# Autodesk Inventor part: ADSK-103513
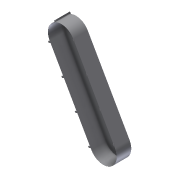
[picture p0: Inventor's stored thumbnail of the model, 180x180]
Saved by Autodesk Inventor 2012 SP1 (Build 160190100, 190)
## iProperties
Shininess: 20.0
Created: 2001-03
Part Number: ADSK-103513
Document SubType Name: Modeling
Designer: Administrator
Stock Number: ADSK-103513
Density: 1 g/cm^3
Material: Default
Density: 0.0
Volumn: 0.0
Area: 0.0
PropertySet Name: Model Information
Control State: 0
Master: False
Checked Out: False
Author: Administrator
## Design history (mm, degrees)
sketch "Sketch1"
  geometry: L1 (158.935, 142.34)-(783.961, -963.211); L2 (-194.841, -57.668)-(430.185, -1163.219); L3 (-17.953, 42.336)-(607.073, -1063.215); A1 r 203.2 centre (-17.953, 42.336) between (158.935, 142.34) and (-194.841, -57.668); A2 r 203.2 centre (607.073, -1063.215) between (430.185, -1163.219) and (783.961, -963.211)
  constraints: 6 end point, 5 point on circle, 4 tangent, 2 centre point
  dimensions: "d11" = 406.4 diameter of A1; "d125" = 1270 distance of L3.end L3.start
extrude "Extrusion1" new body sketch "Sketch1" distance "d5" = 217.17; taper "d6" = 0 deg
shell "Shell1" dims "d7" = 1.5875
sketch "Sketch3"
  geometry: C1 r 50.8 at (17.953, 42.336); A1 r 203.2 centre (17.953, 42.336) between (194.841, -57.668) and (-158.935, 142.34) reference
  constraints: 1 centre point, 1 coincident
  dimensions: "d13" = 101.6 diameter of C1
extrude "Extrusion3" cut sketch "Sketch3" distance "d14" = 25.4; taper "d15" = 0 deg
sketch "Sketch4"
  geometry: L1 (-1.587, 45.689)-(-217.17, 45.689) reference; L2 (-217.17, 45.689)-(-223.52, 45.689); L3 (-223.52, 45.689)-(-198.12, 45.689); L4 (-198.12, 45.689)-(-198.12, 20.289); L5 (-198.12, 20.289)-(-223.52, 20.289); L6 (-223.52, 20.289)-(-223.52, 45.689)
  constraints: 10 end point, 2 parallel, 1 collinear, 1 horizontal, 1 perpendicular
  dimensions: "d18" = 6.35 distance of L1.end L2.end; "d19" = 25.4 distance between parallel lines of L1 L5; "d20" = 25.4 distance between parallel lines of L4 L6
extrude "Extrusion4" join sketch "Sketch4" distance "d21" = 3.175; taper "d22" = 0 deg
sketch "Sketch5"
  geometry: L1 (223.52, 45.689)-(223.52, 20.289) reference; L2 (217.17, 45.689)-(223.52, 45.689) reference; L3 (223.52, 20.289)-(220.345, 20.289); L4 (220.345, 20.289)-(220.345, 45.689); L5 (220.345, 45.689)-(223.52, 45.689); L6 (223.52, 45.689)-(223.52, 20.289)
  constraints: 8 end point, 2 parallel, 1 horizontal, 1 midpoint, 1 perpendicular
  dimensions: "d23" = 3.175 distance between parallel lines of L6 L4 (derived)
extrude "Extrusion5" join sketch "Sketch5" distance "d24" = 22.225; taper "d25" = 0 deg
sketch "Sketch6"
  geometry: L1 (-25.4, 25.4)-(-25.4, 0) reference; L2 (-25.4, 0)-(0, 0) reference; 1 further point
  dimensions: "d26" = 9.525 distance from line of L1 point (-15.875, 12.7); "d27" = 12.7 distance from line of L2 point (-15.875, 12.7)
hole "Hole1" sketch "Sketch6" at (-15.875, 12.7) diameter "d28" = 7.9375; stored, may be unused: countersink angle "d32" = 60 deg, drill point angle "d34" = 118 deg; dims "d29" = 12.7, "d30" = 9.525, "d31" = 6.35, "d33" = 19.05
pattern_linear "Rectangular Pattern1" dims "d37" = 406.4
sketch "Sketch7"
  geometry: L1 (0, 0)-(215.583, 0) reference; L2 (196.533, 0)-(221.933, 0); L3 (221.933, 0)-(221.933, -25.4); L4 (221.933, -25.4)-(196.533, -25.4); L5 (196.533, -25.4)-(196.533, 0); 1 further point; 1 other entity
  constraints: 8 end point, 2 parallel, 1 horizontal, 1 perpendicular, 1 point on line, 1 other
  dimensions: "d38" = 25.4 distance of L2.end L3.end; "d39" = 25.4 distance of L3.end L4.end; "d40" = 6.35 dimension on L3
extrude "Extrusion6" join sketch "Sketch7" distance "d41" = 3.175; taper "d42" = 0 deg
sketch "Sketch8"
  geometry: L1 (-221.933, -25.4)-(-221.933, 0) reference; L2 (-215.583, -25.4)-(-221.933, -25.4) reference; L3 (-221.933, 0)-(-218.758, 0); L4 (-218.758, 0)-(-218.758, -25.4); L5 (-218.758, -25.4)-(-221.933, -25.4); L6 (-221.933, -25.4)-(-221.933, 0)
  constraints: 8 end point, 2 parallel, 1 horizontal, 1 midpoint, 1 perpendicular
extrude "Extrusion7" join sketch "Sketch8" distance "d43" = 22.225; taper "d44" = 0 deg
sketch "Sketch9"
  geometry: L1 (25.4, 0)-(25.4, 25.4) reference; L2 (25.4, 25.4)-(0, 25.4) reference; 1 further point
  dimensions: "d45" = 12.7 distance from line of L2 point (15.875, 12.7); "d46" = 9.525 distance from line of L1 point (15.875, 12.7)
hole "Hole2" sketch "Sketch9" at (15.875, 12.7) diameter "d47" = 7.9375; stored, may be unused: countersink angle "d51" = 60 deg, drill point angle "d53" = 118 deg; dims "d48" = 12.7, "d49" = 9.525, "d50" = 6.35, "d52" = 19.05
pattern_linear "Rectangular Pattern2" dims "d56" = 406.4
sketch "Sketch10"
  geometry: L1 (194.841, -57.668)-(-430.185, -1163.219) reference; L2 (17.953, 42.336)-(-647.399, -1134.544); L3 (17.953, 42.336)-(117.957, 219.224); L4 (-647.399, -1134.544)-(-707.077, -1240.103); L5 (-708.456, -1239.316)-(-648.781, -1133.762); L6 (-648.781, -1133.762)-(16.571, 43.117); L7 (16.571, 43.117)-(116.575, 220.005); L8 (-705.692, -1240.879)-(-646.017, -1135.325); L9 (-646.017, -1135.325)-(19.335, 41.555); L10 (19.335, 41.555)-(119.339, 218.443); L11 (116.575, 220.005)-(119.339, 218.443); L12 (-745.437, -1304.728)-(-743.422, -1307.615); L13 (-708.456, -1239.316)-(-705.692, -1240.879); A1 r 203.2 centre (17.953, 42.336) between (194.841, -57.668) and (-158.935, 142.34) reference; A2 r 203.2 centre (-607.073, -1063.215) between (-783.961, -963.211) and (-430.185, -1163.219) reference
  constraints: 24 end point, 6 collinear, 4 point on circle, 1 parallel, 1 perpendicular, 2 other
  dimensions: "d57" = 1.5875 distance between parallel lines of L2 L6; "d58" = 1.5875 distance between parallel lines of L9 L2
extrude "Extrusion8" join sketch "Sketch10" distance "d59" = 19.05; taper "d60" = 0 deg
sketch "Sketch11"
  geometry: C1 r 50.8 at (5.207, 45.689) reference
extrude "Extrusion9" cut sketch "Sketch11" distance "d61" = 25.4; taper "d62" = 0 deg
sketch "Sketch12"
  geometry: L1 (-27.593, 19.836)-(-124.114, -150.892); L2 (-124.114, -150.892)-(-74.365, -179.018); L3 (-74.365, -179.018)-(22.157, -8.29); A1 r 203.2 centre (17.953, 42.336) between (116.572, 220) and (-158.935, 142.34) reference; A2 r 50.8 centre (17.953, 42.336) between (41.56, 87.318) and (-8.418, -1.083) reference; A3 r 50.8 centre (17.953, 42.336) between (-27.593, 19.836) and (22.157, -8.29)
  constraints: 6 end point, 4 point on circle, 1 centre point, 1 coincident, 1 concentric, 1 parallel, 1 perpendicular
  dimensions: "d65" = 238.125 distance from line of A1.centre L2; "d126" = 57.15 distance between parallel lines of L3 L1; "d127" = 28.575 distance from line of L3 A1.centre (= 0.5 x d126)
extrude "Extrusion10" cut sketch "Sketch12" stored distance "d66" = 50.8; taper "d67" = 0 deg
sketch "Sketch13"
  geometry: L1 (19.05, 0)-(19.05, 152.425) reference; L2 (0, 152.425)-(19.05, 152.425) reference; 2 further points
  dimensions: "d68" = 139.7 distance of point (11.113, 6.375) point (11.113, 146.075); "d69" = 6.35 distance from line of L2 point (11.113, 146.075); "d70" = 7.9375 distance from line of L1 point (11.113, 146.075); "d71" = 7.9375 distance from line of L1 point (11.113, 6.375)
hole "Hole3" sketch "Sketch13" at (11.113, 146.075), (11.113, 6.375) diameter "d72" = 6.35; stored, may be unused: countersink angle "d76" = 60 deg, drill point angle "d78" = 118 deg; dims "d73" = 12.7, "d74" = 9.525, "d75" = 6.35, "d77" = 19.05
sketch "Sketch14"
  geometry: 5 further points
  dimensions: "d79" = 9.525 vertical distance of point (19.05, -192.436) point (11.113, -201.961); "d81" = 330.2 distance of point (11.113, -201.961) point (11.113, -532.161); "d82" = 330.2 distance of point (11.113, -532.161) point (11.113, -862.361); "d83" = 330.2 distance of point (11.113, -1192.561) point (11.113, -862.361)
hole "Hole4" sketch "Sketch14" at (11.113, -201.961), (11.113, -532.161), (11.113, -862.361), (11.113, -1192.561) diameter "d89" = 6.35; stored, may be unused: countersink angle "d93" = 60 deg, drill point angle "d95" = 118 deg; dims "d90" = 12.7, "d91" = 9.525, "d92" = 6.35, "d94" = 19.05
sketch "Sketch15"
  geometry: L1 (3.175, 19.05)-(0, 19.05) reference; L2 (0, 0)-(0, 19.05) reference; L3 (0, 0)-(1.588, 0) reference; L4 (1.588, 0)-(3.175, 0) reference; L5 (3.175, 0)-(3.175, 19.05) reference
extrude "Extrusion11" join sketch "Sketch15" distance "d96" = 19.05; taper "d97" = 0 deg
sketch "Sketch16"
  geometry: L1 (-116.572, 220)-(-125.95, 236.589) reference; L2 (-125.95, 236.589)-(-128.714, 235.026) reference; L3 (-119.336, 218.437)-(-128.714, 235.026) reference; A1 r 203.2 centre (-17.953, 42.336) between (-116.572, 220) and (-119.336, 218.437) reference
extrude "Extrusion12" join sketch "Sketch16" stored distance "d98" = 19.05; taper "d99" = 0 deg
sketch "Sketch17"
  geometry: L1 (236.22, 19.056)-(0, 19.056) reference; L2 (0, 19.056)-(0, 0) reference; 1 further point
  dimensions: "d100" = 12.7 distance from line of L2 point (12.7, 11.119); "d101" = 7.9375 distance from line of L1 point (12.7, 11.119)
hole "Hole5" sketch "Sketch17" at (12.7, 11.119) diameter "d102" = 6.35; stored, may be unused: countersink angle "d106" = 60 deg, drill point angle "d108" = 118 deg; dims "d103" = 12.7, "d104" = 9.525, "d105" = 6.35, "d107" = 19.05
body "Solid1"
other parameters: "d124" = 1176.87949 (derived)
